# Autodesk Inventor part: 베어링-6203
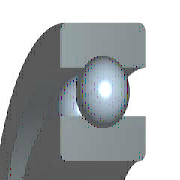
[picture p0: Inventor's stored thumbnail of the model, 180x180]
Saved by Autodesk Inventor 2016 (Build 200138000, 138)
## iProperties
IsCustomPart: 0
Created: 2016-05
Part Number: 베어링-6203
Material: 강철, 연강
Description: 깊은 그루브 볼 베어링
Document SubType Name: Modeling
Standard: KS B 2023
Designer: mduedu
Standards Organization: KS
Language: ko-KR
Size Designation: 6203 - 17 x 40 x 12
Categories: <MemberInstance><Categories><Category DisplayName="샤프트 부품" InternalName="7f7aeb1f-a693-4053-b835-cee3144e0d98" Mnemonic="SHFT"><Category DisplayName="베어링" Inter
Density: 1 g/cm^3
Appearance: 노란색
Author: mduedu
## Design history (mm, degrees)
sketch "스케치" dims "d0" = 5.98 (= -0.26 x WD + 0.26 x BD)
  geometry: L1 (3.01, 14.25)-(8.99, 14.25); L2 (6, 14.25)-(6, 11.26); L3 (6, 14.25)-(6, 17.24); L4 (3.778, 12.249)-(0, 12.249); L5 (0, 8.5)-(12, 8.5); L6 (3.778, 16.251)-(0, 16.251); L7 (0, 20)-(12, 20); L8 (12, 8.5)-(12, 12.249); L9 (8.222, 12.249)-(12, 12.249); L10 (8.222, 16.251)-(12, 16.251); L11 (12, 20)-(12, 16.251); L12 (-1.4, 0)-(8.4, 0) reference; L13 (0, -0.3)-(0, 5.3) reference
  constraints: 22 end point, 4 point on line, 2 collinear, 2 perpendicular, 2 symmetric about line, 1 midpoint, 1 parallel, 14 other
  dimensions: "d9" = 17 diameter of L5 L12 (= WD); "d11" = 40 diameter of L7 L12 (= BD); "d12" = 12 distance between parallel lines of L8 L13 (= KB); "d13" = 24.498 diameter of L9 L12 (= 0.326 x BD + 0.674 x WD)
revolve "본체" stored, may be unused: angle "d6" = 90 deg
revolve "볼" stored, may be unused: angle "d7" = 90 deg
pattern_circular "IDS_ARRAYBALL[SIMPL:T]" dims angle "d3" = 360 deg
body "Solid1"
fillet "모깎기1" dims "d1" = 0.6 (= KRS)
other parameters: "WD" = 17 [user parameter; used in 5 equation terms], "BD" = 40 [user parameter; used in 5 equation terms], "KB" = 12 [user parameter; used in 1 equation term], "KRS" = 0.6 [user parameter; used in 1 equation term], "d4" = 0, "d5" = 0, "d8" = 0, "d14" = 0, "d15" = 0, "BBA" = 0 [user parameter], "BC0" = 4750000 [user parameter], "BC" = 9560000 [user parameter], "WR" = 8.5 (= 0.5 x WD) [user parameter]
